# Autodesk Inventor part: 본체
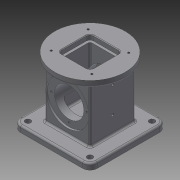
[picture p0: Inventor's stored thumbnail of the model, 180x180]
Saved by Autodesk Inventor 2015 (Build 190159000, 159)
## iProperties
Created: 2021-05
Part Number: 본체
Material: 일반
Document SubType Name: Modeling
Designer: 1019876
Density: 1 g/cm^3
Appearance: 기본값
Author: 1019876
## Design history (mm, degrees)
sketch "스케치1"
  geometry: L1 (-62.5, -62.5)-(62.5, -62.5); L2 (62.5, -62.5)-(62.5, 62.5); L3 (62.5, 62.5)-(-62.5, 62.5); L4 (-62.5, 62.5)-(-62.5, -62.5); L5 (-62.5, -62.5)-(62.5, 62.5); L6 (62.5, -62.5)-(-62.5, 62.5); 1 further point
  constraints: 12 end point, 2 midpoint, 2 parallel, 1 horizontal, 1 perpendicular
  dimensions: "d0" = 125 distance of L3.end L2.end; "d1" = 125 distance of L2.end L1.end
extrude "돌출1" new body sketch "스케치1" distance "d2" = 10; taper "d3" = 0 deg
sketch "스케치2"
  geometry: L1 (37, -37)-(-37, -37); L2 (-37, -37)-(-37, 37); L3 (-37, 37)-(37, 37); L4 (37, 37)-(37, -37); L5 (37, -37)-(-37, 37); L6 (-37, -37)-(37, 37); 1 further point
  constraints: 12 end point, 2 midpoint, 2 parallel, 1 horizontal, 1 perpendicular
  dimensions: "d4" = 74 distance of L2.end L3.end; "d5" = 74 distance of L1.end L2.end
extrude "돌출2" join sketch "스케치2" distance "d6" = 88; taper "d7" = 0 deg
sketch "스케치3"
  geometry: C1 r 57.5 at (0, 0); 1 further point
  constraints: 1 centre point, 1 coincident
  dimensions: "d8" = 57.5 radius of C1
extrude "돌출3" join sketch "스케치3" distance "d9" = 10; taper "d10" = 0 deg
sketch "스케치4"
  geometry: L1 (-26, -26)-(26, -26); L2 (26, -26)-(26, 26); L3 (26, 26)-(-26, 26); L4 (-26, 26)-(-26, -26); L5 (-26, -26)-(26, 26); L6 (26, -26)-(-26, 26); C1 r 57.5 at (0, 0) reference
  constraints: 12 end point, 2 midpoint, 2 parallel, 1 horizontal, 1 perpendicular
  dimensions: "d11" = 52 distance of L3.end L2.end; "d12" = 52 distance of L2.end L1.end
extrude "돌출4" cut sketch "스케치4" distance "d13" = 8; taper "d14" = 0 deg
sketch "스케치5"
  geometry: L1 (-25.5, -10)-(99.5, -10) reference; C1 r 35 at (37, 44); 2 further points
  constraints: 1 centre point, 1 midpoint, 1 vertical alignment
  dimensions: "d15" = 35 radius of C1; "d16" = 54 distance from line of L1 C1.centre
extrude "돌출5" cut sketch "스케치5" distance "d17" = 3; taper "d18" = 0 deg
sketch "스케치6"
  geometry: C1 r 35 at (0, 0) reference; 1 further point
hole "구멍1" sketch "스케치6" at (0, 0) diameter "d19" = 48; stored, may be unused: countersink angle "d23" = 90 deg, drill point angle "d25" = 118 deg; dims "d20" = 6, "d21" = 4, "d22" = 2, "d24" = 8
sketch "스케치7"
  geometry: L1 (0, 0)-(0, 29); C1 r 35 at (0, 0) reference; 1 further point
  constraints: 2 end point, 1 vertical
  dimensions: "d26" = 29 distance of L1.start L1.end
hole "구멍2" sketch "스케치7" at (0, 29) diameter "d27" = 3.242; stored, may be unused: countersink angle "d31" = 90 deg, drill point angle "d33" = 118 deg; dims "d28" = 8, "d29" = 4, "d30" = 2, "d32" = 10
sketch "스케치8"
  geometry: C1 r 28 at (0, 0); 1 further point
  constraints: 1 centre point, 1 coincident
  dimensions: "d37" = 28 radius of C1
extrude "돌출6" cut sketch "스케치8" distance "d38" = 18; taper "d39" = -10 deg
sketch "스케치9"
  geometry: L1 (-22, -22)-(22, -22); L2 (22, -22)-(22, 22); L3 (22, 22)-(-22, 22); L4 (-22, 22)-(-22, -22); L5 (-22, -22)-(22, 22); L6 (22, -22)-(-22, 22); 1 further point
  constraints: 12 end point, 2 midpoint, 2 parallel, 1 horizontal, 1 perpendicular
  dimensions: "d40" = 44 distance of L3.end L2.end; "d41" = 44 distance of L2.end L1.end
extrude "돌출7" cut sketch "스케치9" distance "d42" = 74; taper "d43" = 0 deg
fillet "모깎기1" dims "d44" = 12
hole "구멍3" diameter "d47" = 9; stored, may be unused: countersink angle "d51" = 90 deg, drill point angle "d53" = 118 deg; dims "d45" = 10, "d46" = 10, "d48" = 8, "d49" = 4, "d50" = 2, "d52" = 10
hole "구멍4" diameter "d56" = 9; stored, may be unused: countersink angle "d60" = 90 deg, drill point angle "d62" = 118 deg; dims "d54" = 10, "d55" = 10, "d57" = 8, "d58" = 4, "d59" = 2, "d61" = 10
hole "구멍5" diameter "d65" = 9; stored, may be unused: countersink angle "d69" = 90 deg, drill point angle "d71" = 118 deg; dims "d63" = 10, "d64" = 10, "d66" = 8, "d67" = 4, "d68" = 2, "d70" = 10
hole "구멍6" diameter "d74" = 9; stored, may be unused: countersink angle "d78" = 90 deg, drill point angle "d80" = 118 deg; dims "d72" = 10, "d73" = 10, "d75" = 8, "d76" = 4, "d77" = 2, "d79" = 10
sketch "스케치10"
  geometry: C1 r 57.5 at (0, 0) reference; 4 further points
  constraints: 2 horizontal alignment, 2 vertical alignment
  dimensions: "d81" = 60 distance of point (33, -30) point (33, 30); "d82" = 30 vertical distance of C1.centre point (33, 30); "d83" = 66 distance of point (33, 30) point (-33, 30); "d84" = 33 horizontal distance of C1.centre point (-33, 30)
hole "구멍7" sketch "스케치10" at (-33, 30), (33, 30), (-33, -30), (33, -30) diameter "d85" = 3.242; stored, may be unused: countersink angle "d89" = 90 deg, drill point angle "d91" = 118 deg; dims "d86" = 8, "d87" = 4, "d88" = 2, "d90" = 10
sketch "스케치11"
  geometry: L1 (10, -13.5)-(10, 87.5) reference; 4 further points
  constraints: 2 horizontal alignment, 1 midpoint
  dimensions: "d92" = 43 distance of point (-27, 37) point (-70, 37); "d93" = 37 distance from line of L1 point (-27, 37)
hole "구멍8" sketch "스케치11" at (-70, 37), (-27, 37) diameter "d94" = 4.134; stored, may be unused: countersink angle "d98" = 90 deg, drill point angle "d100" = 118 deg; dims "d95" = 10, "d96" = 4, "d97" = 2, "d99" = 20
fillet "모깎기2" dims "d101" = 6
fillet "모깎기3" dims "d102" = 3
fillet "모깎기4" dims "d103" = 3
fillet "모깎기5" dims "d104" = 3
fillet "모깎기6" dims "d105" = 3
fillet "모깎기7" dims "d106" = 3
chamfer "모따기1" distance "d107" = 1; stored, may be unused: second distance "d108" = 2, angle "d109" = 45 deg
node "솔리드1"
mirror "대칭1"
pattern_circular "원형 패턴1" dims angle "d35" = 360 deg
mirror "대칭2"
